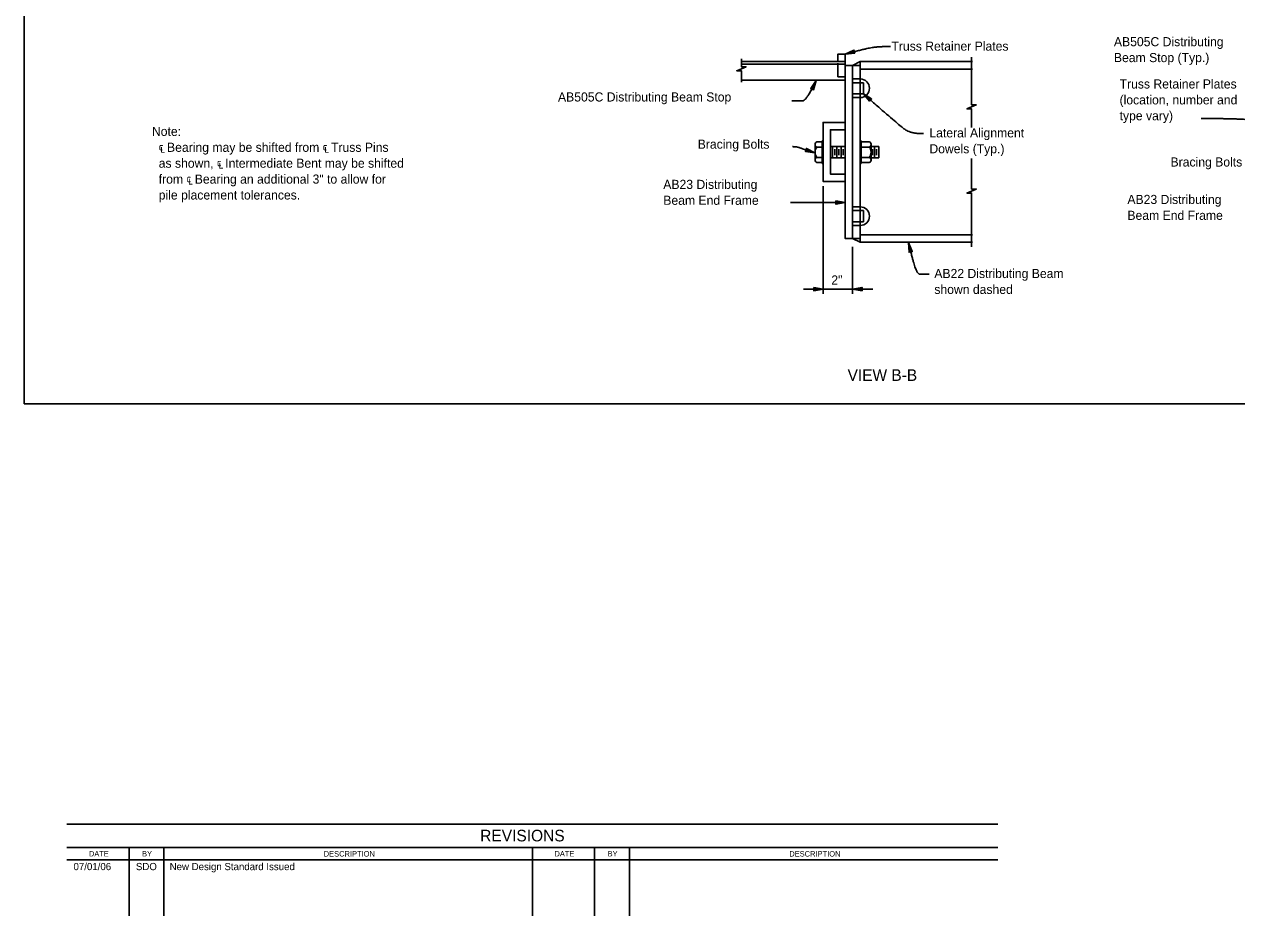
# Model space of a CAD drawing. Extents: x 112363.6 to 112390.2, y 109543.2 to 109558.
# Drawn here: x 112363.65 to 112373.71, y 109543.17 to 109550.57 of the extents above; entities that cross this region are included whole.
import ezdxf

# ---------------------------------------------------------------- set-up
doc = ezdxf.new("R2010")
doc.units = 0
for name, color, linetype in [('ActivePts-ConstElements', 7, 'Continuous'), ('Border', 7, 'Continuous'), ('Dimension', 7, 'Continuous'), ('SteelMisc', 7, 'Continuous'), ('SteelMisc_h', 7, 'Continuous'), ('Symbols', 7, 'Continuous'), ('TextStructures', 7, 'Continuous')]:
    doc.layers.add(name, color=color, linetype=linetype)

msp = doc.modelspace()

# ---------------------------------------------------------------- linework, layer by layer
at = {"layer": 'ActivePts-ConstElements'}
msp.add_lwpolyline([(112363.648, 109547.417), (112379.042, 109547.417), (112379.042, 109557.147), (112363.648, 109557.147)], close=True, dxfattribs=at)
at = {"layer": 'Border'}
for p, q in [((112371.731, 109543.928), (112364.002, 109543.928)), ((112371.731, 109543.734), (112364.002, 109543.734)), ((112364.518, 109543.734), (112364.518, 109543.166)), ((112364.808, 109543.734), (112364.808, 109543.166)), ((112367.867, 109543.734), (112367.867, 109543.166)), ((112368.383, 109543.734), (112368.383, 109543.166)), ((112368.673, 109543.734), (112368.673, 109543.166)), ((112364.002, 109543.632), (112371.731, 109543.632))]:
    msp.add_line(p, q, dxfattribs=at)
at = {"layer": 'Dimension'}
for p, q in [((112370.28, 109549.226), (112370.28, 109548.332)), ((112370.008, 109549.089), (112370.464, 109549.089)), ((112370.525, 109548.721), (112370.525, 109548.332)), ((112370.117, 109548.37), (112370.692, 109548.37))]:
    msp.add_line(p, q, dxfattribs=at)
for points in [[(112370.464, 109550.321), (112370.543, 109550.329), (112370.536, 109550.355)], [(112370.221, 109550.103), (112370.177, 109550.037), (112370.201, 109550.026)], [(112370.615, 109549.992), (112370.664, 109549.931), (112370.682, 109549.95)], [(112370.212, 109549.502), (112370.141, 109549.538), (112370.133, 109549.513)], [(112370.464, 109549.089), (112370.386, 109549.102), (112370.386, 109549.075)], [(112370.99, 109548.756), (112370.994, 109548.676), (112371.02, 109548.682)], [(112370.202, 109548.384), (112370.28, 109548.37), (112370.202, 109548.357)], [(112370.603, 109548.357), (112370.525, 109548.37), (112370.603, 109548.384)]]:
    msp.add_lwpolyline(points, close=True, dxfattribs=at)
for points in [[(112370.84, 109550.385), (112370.765, 109550.385), (112370.646, 109550.372), (112370.464, 109550.321)], [(112373.417, 109549.787), (112373.683, 109549.787), (112374.037, 109549.764), (112374.8, 109549.93), (112374.875, 109550.002), (112375.078, 109550.134)], [(112370.019, 109549.933), (112370.07, 109549.933), (112370.144, 109549.933), (112370.221, 109550.103)], [(112371.112, 109549.661), (112371.015, 109549.661), (112370.921, 109549.72), (112370.615, 109549.992)], [(112370.027, 109549.553), (112370.063, 109549.553), (112370.111, 109549.534), (112370.212, 109549.502)], [(112371.159, 109548.494), (112371.102, 109548.494), (112371.064, 109548.494), (112371.022, 109548.612), (112370.99, 109548.756)]]:
    msp.add_open_spline(points, degree=2, dxfattribs=at)
at = {"layer": 'SteelMisc'}
for p, q in [((112370.464, 109550.259), (112369.602, 109550.259)), ((112370.525, 109550.228), (112370.588, 109550.259)), ((112370.525, 109550.228), (112370.588, 109550.228)), ((112370.588, 109548.759), (112370.588, 109550.259)), ((112370.588, 109550.259), (112371.519, 109550.259)), ((112370.588, 109550.197), (112371.519, 109550.197)), ((112370.464, 109550.104), (112369.602, 109550.104)), ((112370.525, 109550.116), (112370.588, 109550.116)), ((112370.615, 109550.084), (112370.525, 109550.084)), ((112370.615, 109549.992), (112370.615, 109550.084)), ((112370.525, 109549.992), (112370.615, 109549.992)), ((112370.525, 109549.961), (112370.588, 109549.961)), ((112370.213, 109549.57), (112370.213, 109549.444)), ((112370.229, 109549.593), (112370.272, 109549.593)), ((112370.272, 109549.55), (112370.229, 109549.55)), ((112370.272, 109549.601), (112370.28, 109549.601)), ((112370.272, 109549.601), (112370.272, 109549.413)), ((112370.341, 109549.554), (112370.464, 109549.554)), ((112370.359, 109549.554), (112370.359, 109549.46)), ((112370.376, 109549.532), (112370.376, 109549.482)), ((112370.394, 109549.554), (112370.394, 109549.46)), ((112370.411, 109549.532), (112370.411, 109549.482)), ((112370.429, 109549.554), (112370.429, 109549.46)), ((112370.446, 109549.531), (112370.446, 109549.482)), ((112370.596, 109549.601), (112370.588, 109549.601)), ((112370.596, 109549.601), (112370.596, 109549.413)), ((112370.663, 109549.593), (112370.596, 109549.593)), ((112370.596, 109549.55), (112370.663, 109549.55)), ((112370.678, 109549.57), (112370.678, 109549.444)), ((112370.678, 109549.554), (112370.742, 109549.554)), ((112370.689, 109549.532), (112370.689, 109549.482)), ((112370.707, 109549.554), (112370.707, 109549.46)), ((112370.724, 109549.531), (112370.724, 109549.482)), ((112370.742, 109549.554), (112370.742, 109549.46)), ((112370.229, 109549.464), (112370.272, 109549.464)), ((112370.229, 109549.421), (112370.272, 109549.421)), ((112370.341, 109549.46), (112370.464, 109549.46)), ((112370.663, 109549.464), (112370.596, 109549.464)), ((112370.663, 109549.421), (112370.596, 109549.421)), ((112370.678, 109549.46), (112370.742, 109549.46)), ((112370.272, 109549.413), (112370.28, 109549.413)), ((112370.596, 109549.413), (112370.588, 109549.413)), ((112370.525, 109549.053), (112370.588, 109549.053)), ((112370.525, 109549.022), (112370.615, 109549.022)), ((112370.615, 109549.022), (112370.615, 109548.93)), ((112370.615, 109548.93), (112370.525, 109548.93)), ((112370.615, 109548.93), (112370.588, 109548.93)), ((112370.525, 109548.899), (112370.588, 109548.899)), ((112370.588, 109548.82), (112371.519, 109548.82)), ((112370.525, 109548.79), (112370.588, 109548.79)), ((112370.525, 109548.79), (112370.588, 109548.759)), ((112370.588, 109548.759), (112371.519, 109548.759))]:
    msp.add_line(p, q, dxfattribs=at)
msp.add_lwpolyline([(112370.402, 109550.259), (112370.402, 109550.321), (112370.464, 109550.321), (112370.464, 109550.134)], dxfattribs=at)
for points in [[(112370.525, 109548.79), (112370.464, 109548.79), (112370.464, 109550.228), (112370.525, 109550.228)], [(112370.464, 109549.754), (112370.28, 109549.754), (112370.28, 109549.264), (112370.464, 109549.264), (112370.464, 109549.325), (112370.341, 109549.325), (112370.341, 109549.693), (112370.464, 109549.693)]]:
    msp.add_lwpolyline(points, close=True, dxfattribs=at)
for centre, radius, start, end in [((112370.588, 109550.038), 0.0771, 270.0279, 89.9721), ((112370.235, 109549.571), 0.0224, 107.2558, 183.0154), ((112370.235, 109549.571), 0.0224, 183.0154, 252.7442), ((112370.279, 109549.507), 0.0661, 139.6401, 220.3599), ((112370.656, 109549.571), 0.0224, 356.9846, 72.7442), ((112370.656, 109549.571), 0.0224, 287.2558, 356.9846), ((112370.612, 109549.507), 0.0661, 319.6401, 40.3599), ((112370.235, 109549.443), 0.0224, 107.2558, 176.9846), ((112370.235, 109549.443), 0.0224, 176.9846, 252.7442), ((112370.656, 109549.443), 0.0224, 3.0154, 72.7442), ((112370.656, 109549.443), 0.0224, 287.2558, 3.0154), ((112370.588, 109548.976), 0.0771, 270.0279, 89.9721)]:
    msp.add_arc(centre, radius, start, end, dxfattribs=at)
at = {"layer": 'SteelMisc_h'}
msp.add_line((112370.464, 109550.238), (112369.602, 109550.238), dxfattribs=at)
for points in [[(112370.402, 109550.134), (112370.402, 109550.245)], [(112370.464, 109550.134), (112370.402, 109550.134)]]:
    msp.add_lwpolyline(points, dxfattribs=at)
at = {"layer": 'Symbols'}
for points in [[(112369.602, 109550.088), (112369.602, 109550.184), (112369.563, 109550.184), (112369.64, 109550.217), (112369.602, 109550.217), (112369.602, 109550.283)], [(112371.513, 109549.712), (112371.513, 109549.867), (112371.474, 109549.867), (112371.551, 109549.9), (112371.513, 109549.9), (112371.513, 109550.297)], [(112371.513, 109548.72), (112371.513, 109549.167), (112371.474, 109549.167), (112371.551, 109549.201), (112371.513, 109549.201), (112371.513, 109549.456)]]:
    msp.add_lwpolyline(points, dxfattribs=at)

# ---------------------------------------------------------------- texts
at = {"layer": 'Dimension'}
msp.add_text('2"', height=0.0756, dxfattribs=at).set_placement((112370.348, 109548.408))
at = {"layer": 'TextStructures'}
for s, height, p in [('Truss Retainer Plates ', 0.0756, (112370.847, 109550.35)), ('AB505C Distributing ', 0.0756, (112372.694, 109550.387)), ('Beam Stop (Typ.)', 0.0756, (112372.694, 109550.255)), ('Truss Retainer Plates ', 0.0756, (112372.741, 109550.036)), ('AB505C Distributing Beam Stop', 0.0756, (112368.079, 109549.928)), ('(location, number and ', 0.0756, (112372.741, 109549.904)), ('type vary)', 0.0756, (112372.741, 109549.772)), ('Note:', 0.0756, (112364.708, 109549.642)), ('Lateral Alignment ', 0.0756, (112371.162, 109549.63)), ('  ℄ Bearing may be shifted from ℄ Truss Pins ', 0.0756, (112364.708, 109549.51)), ('Bracing Bolts', 0.0756, (112369.239, 109549.536)), ('Dowels (Typ.)', 0.0756, (112371.162, 109549.498)), ('  as shown, ℄ Intermediate Bent may be shifted', 0.0756, (112364.708, 109549.378)), ('Bracing Bolts', 0.0756, (112373.164, 109549.388)), ('  from ℄ Bearing an additional 3" to allow for ', 0.0756, (112364.708, 109549.246)), ('AB23 Distributing ', 0.0756, (112368.953, 109549.202)), ('  pile placement tolerances.', 0.0756, (112364.708, 109549.114)), ('Beam End Frame', 0.0756, (112368.953, 109549.07)), ('AB23 Distributing ', 0.0756, (112372.806, 109549.077)), ('Beam End Frame', 0.0756, (112372.806, 109548.945)), ('AB22 Distributing Beam ', 0.0756, (112371.203, 109548.462)), ('shown dashed', 0.0756, (112371.203, 109548.33)), ('VIEW B-B', 0.096, (112370.483, 109547.608)), ('REVISIONS', 0.0963, (112367.433, 109543.784)), ('BY', 0.045, (112364.626, 109543.659)), ('BY', 0.045, (112368.491, 109543.659)), ('07/01/06', 0.06, (112364.057, 109543.545)), ('SDO', 0.06, (112364.575, 109543.545)), ('New Design Standard Issued', 0.06, (112364.855, 109543.545))]:
    msp.add_text(s, height=height, dxfattribs=at).set_placement(p)
for s, height, rotation, p in [('DATE', 0.0448, 359.8693, (112364.185, 109543.659)), ('DESCRIPTION', 0.04503, 0.0498, (112366.134, 109543.658)), ('DATE', 0.0448, 359.8693, (112368.05, 109543.659)), ('DESCRIPTION', 0.04503, 0.0498, (112369.999, 109543.658))]:
    msp.add_text(s, height=height, rotation=rotation, dxfattribs=at).set_placement(p)

doc.saveas('drawing.dxf')
